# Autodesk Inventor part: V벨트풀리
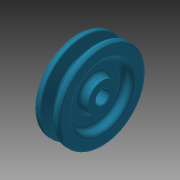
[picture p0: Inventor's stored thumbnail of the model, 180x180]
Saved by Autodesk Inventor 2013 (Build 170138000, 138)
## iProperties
Created: 2015-11
Part Number: V벨트풀리
Material: 강철, 탄소
Document SubType Name: Modeling
Designer: mduedu
Density: 7.87 g/cm^3
Mass: 380.065 g
Surface Area: 160.69 cm^2
Volume: 48.2929 cm^3
Author: mduedu
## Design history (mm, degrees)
sketch "스케치1"
  geometry: L1 (-9.5, 0)-(9.5, 0); L2 (0, 0)-(0, 35.7); L3 (-4.825, 35.7)-(-9.5, 35.7); L4 (-9.5, 35.7)-(-9.5, 0); L5 (0, 26.7)-(-2.074, 26.7); L6 (-2.074, 26.7)-(-4.825, 35.7); L7 (4.825, 35.7)-(9.5, 35.7); L8 (9.5, 35.7)-(9.5, 0); L9 (0, 26.7)-(2.074, 26.7); L10 (2.074, 26.7)-(4.825, 35.7); L11 (-9.5, 33)-(9.5, 33); 3 further points
  constraints: 22 end point, 7 point on line, 4 perpendicular, 3 symmetric about line, 1 coincident, 1 horizontal, 1 horizontal alignment, 1 midpoint, 1 vertical
  dimensions: "d0" = 19 distance of L1.start L1.end; "d2" = 71.4 diameter of L2.end L1 (derived); "d3" = 34 deg angle of L10 L6; "d4" = 6.3 distance between parallel lines of L11 L9; "d5" = 2.7 distance between parallel lines of L7 L11; "d6" = 8 distance of point (4, 33) point (-4, 33); "d7" = 66 diameter of L11 L1
revolve "회전1" sketch "스케치1" stored, may be unused: angle "d8" = 90 deg
sketch "스케치2"
  geometry: C1 r 22 at (0, 0); C2 r 11 at (0, 0); 1 further point
  constraints: 2 centre point, 2 coincident
  dimensions: "d9" = 44 diameter of C1; "d10" = 22 diameter of C2
extrude "돌출1" cut sketch "스케치2" distance "d11" = 6; taper "d12" = 0 deg
fillet "모깎기1" dims "d13" = 3
fillet "모깎기2" dims "d14" = 3
fillet "모깎기3" dims "d15" = 1, "d16" = 0.5, "d17" = 2
hole "구멍1" diameter "d20" = 10; stored, may be unused: countersink angle "d24" = 90 deg, drill point angle "d26" = 118 deg; dims "d18" = 10, "d19" = 10, "d21" = 6, "d22" = 4, "d23" = 2, "d25" = 8
sketch "스케치3"
  geometry: L1 (-1.5, 0)-(1.5, 0); L2 (1.5, 0)-(1.5, 6.4); L3 (1.5, 6.4)-(-1.5, 6.4); L4 (-1.5, 6.4)-(-1.5, 0); 2 further points
  constraints: 8 end point, 2 parallel, 1 coincident, 1 horizontal, 1 midpoint, 1 perpendicular
  dimensions: "d27" = 3 distance of L2.end L3.end; "d29" = 6.4 distance of L3.end L1.start
extrude "돌출2" cut sketch "스케치3" stored distance "d30" = 6; taper "d31" = 0 deg
chamfer "모따기1" distance "d32" = 0.5; stored, may be unused: second distance "d33" = 2, angle "d34" = 45 deg
node "솔리드1"
mirror "대칭1"
